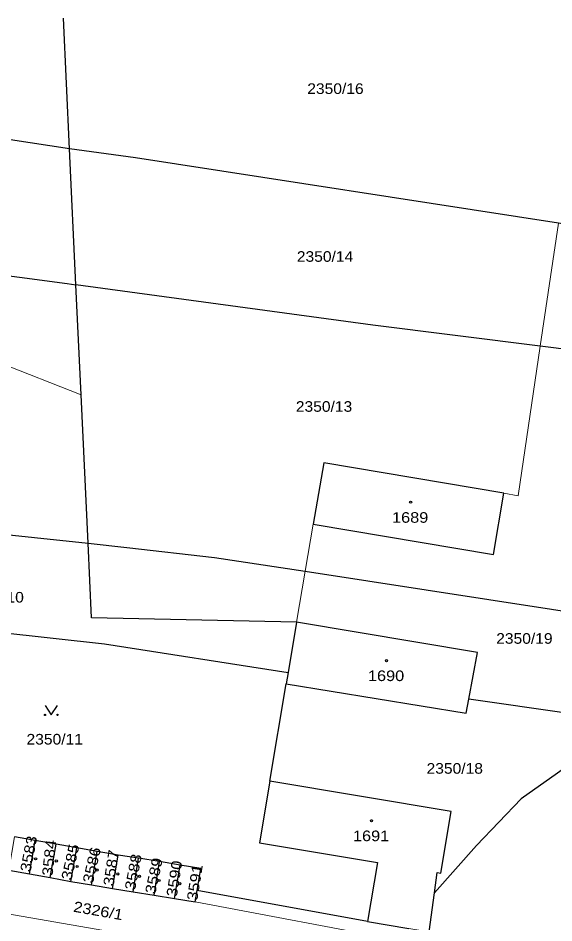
# Model space of a CAD drawing. Extents: x -652394 to -652006, y -1024262 to -1023975.
# Drawn here: x -652262.8 to -652176.9, y -1024121 to -1023975.9 of the extents above; entities that cross this region are included whole.
import ezdxf

# ---------------------------------------------------------------- set-up
doc = ezdxf.new("R2010")
doc.units = 0
doc.header["$LTSCALE"] = 0.46
doc.layers.add('63', color=7, linetype='Continuous', lineweight=25)

msp = doc.modelspace()

# ---------------------------------------------------------------- linework, layer by layer
at = {"layer": '63'}
for p, q in [((-652253.52, -1024018.67), (-652254.55, -1023996.87)), ((-652218.15, -1024072.78), (-652219.51, -1024080.83)), ((-652222.47, -1024098.26), (-652219.82, -1024082.64)), ((-652174.55, -1024087.4), (-652190.57, -1024085.1)), ((-652260.03, -1024107.76), (-652263.39, -1024107.18)), ((-652260.99, -1024113.11), (-652260.03, -1024107.76)), ((-652256.7, -1024108.35), (-652260.03, -1024107.76)), ((-652257.66, -1024113.7), (-652256.7, -1024108.35)), ((-652253.4, -1024108.94), (-652256.7, -1024108.35)), ((-652254.32, -1024114.3), (-652253.4, -1024108.94)), ((-652250.1, -1024109.54), (-652253.4, -1024108.94)), ((-652251.01, -1024114.87), (-652250.1, -1024109.54)), ((-652246.77, -1024110.08), (-652250.1, -1024109.54)), ((-652247.67, -1024115.42), (-652246.77, -1024110.08)), ((-652243.47, -1024110.58), (-652246.77, -1024110.08)), ((-652244.33, -1024115.96), (-652243.47, -1024110.58)), ((-652240.15, -1024111.14), (-652243.47, -1024110.58)), ((-652264.3, -1024112.52), (-652260.99, -1024113.11)), ((-652236.81, -1024111.68), (-652240.15, -1024111.14)), ((-652237.71, -1024117.04), (-652236.81, -1024111.68)), ((-652260.99, -1024113.11), (-652257.66, -1024113.7)), ((-652241.01, -1024116.51), (-652237.71, -1024117.04)), ((-652206.77, -1024120.74), (-652234.11, -1024115.74)), ((-652196.89, -1024122.39), (-652196.06, -1024116.16)), ((-652206.77, -1024120.74), (-652200.18, -1024121.84))]:
    msp.add_line(p, q, dxfattribs=at)
at = {"layer": '63', "lineweight": 13}
for p, q in [((-652179.1, -1024028.51), (-652176.19, -1024008.82)), ((-652316.03, -1024011.45), (-652252.69, -1024036.32)), ((-652182.65, -1024052.49), (-652179.1, -1024028.51)), ((-652184.92, -1024052.11), (-652182.65, -1024052.49)), ((-652216.77, -1024064.61), (-652215.49, -1024057.07)), ((-652218.15, -1024072.78), (-652216.77, -1024064.61)), ((-652306.83, -1024112.26), (-652229.68, -1024125.5))]:
    msp.add_line(p, q, dxfattribs=at)
at = {"layer": '63'}
for points in [[(-652148.27, -1024013.13), (-652170.4, -1024009.72), (-652176.19, -1024008.82), (-652243.97, -1023998.36), (-652254.55, -1023996.87), (-652255.534, -1023975.941)], [(-652254.55, -1023996.87), (-652304.35, -1023989.32), (-652308.54, -1023988.67)], [(-652317.6, -1024010.17), (-652316.1, -1024010.37), (-652254.95, -1024018.48), (-652253.52, -1024018.67)], [(-652251.57, -1024060.11), (-652252.69, -1024036.32), (-652253.52, -1024018.67)], [(-652143.83, -1024032.94), (-652173.61, -1024029.2), (-652179.1, -1024028.51), (-652205.95, -1024025.14), (-652253.52, -1024018.67)], [(-652303.5, -1024054.52), (-652286.04, -1024056.49), (-652251.57, -1024060.11)], [(-652218.15, -1024072.78), (-652251.01, -1024072.09), (-652251.57, -1024060.11)], [(-652251.57, -1024060.11), (-652245.35, -1024060.77), (-652231.31, -1024062.37), (-652216.77, -1024064.61), (-652147.85, -1024075.21)], [(-652312.45, -1024070.27), (-652274.64, -1024073.41), (-652248.96, -1024076.21), (-652219.51, -1024080.83), (-652219.82, -1024082.64)], [(-652190.57, -1024085.1), (-652189.16, -1024077.6), (-652218.15, -1024072.78)], [(-652219.82, -1024082.64), (-652190.99, -1024087.34), (-652190.57, -1024085.1)], [(-652258.48, -1024086.129), (-652257.48, -1024087.63), (-652256.48, -1024086.129)], [(-652168.15, -1024091.02), (-652170.52, -1024092.87), (-652182.16, -1024101.09), (-652189.3, -1024108.53), (-652196.06, -1024116.16)], [(-652222.47, -1024098.26), (-652224.11, -1024108.14), (-652205.17, -1024111.28), (-652206.77, -1024120.74)], [(-652196.06, -1024116.16), (-652195.63, -1024112.89), (-652195.04, -1024112.97), (-652193.37, -1024103.11), (-652222.47, -1024098.26)], [(-652251.01, -1024114.87), (-652247.67, -1024115.42), (-652244.33, -1024115.96), (-652241.01, -1024116.51), (-652240.15, -1024111.14)], [(-652234.11, -1024115.74), (-652233.5, -1024112.24), (-652236.81, -1024111.68)], [(-652257.66, -1024113.7), (-652254.32, -1024114.3), (-652251.01, -1024114.87)], [(-652237.71, -1024117.04), (-652234.43, -1024117.59), (-652234.11, -1024115.74)]]:
    msp.add_lwpolyline(points, dxfattribs=at)
at = {"layer": '63', "lineweight": 13}
for points in [[(-652304.35, -1023989.32), (-652308.54, -1023988.67), (-652308.92, -1023989.69), (-652296.96, -1023994.12), (-652296.17, -1023991.97), (-652292, -1023993.55), (-652294.51, -1024000.29), (-652297.07, -1023999.34), (-652298.69, -1024003.7), (-652306.35, -1024000.82), (-652307.3, -1024008.01), (-652317.85, -1024006.6), (-652317.6, -1024010.17), (-652316.1, -1024010.37), (-652254.95, -1024018.48), (-652253.52, -1024018.67), (-652254.55, -1023996.87)], [(-652243.97, -1023998.36), (-652254.55, -1023996.87), (-652253.52, -1024018.67), (-652205.95, -1024025.14), (-652179.1, -1024028.51), (-652173.61, -1024029.2), (-652143.83, -1024032.94), (-652144.06, -1024031.61), (-652145.01, -1024027.21), (-652151.72, -1024026.09), (-652150.9, -1024021.17), (-652146.15, -1024021.97), (-652146.66, -1024019.59), (-652148.27, -1024013.13), (-652170.4, -1024009.72), (-652176.19, -1024008.82)], [(-652308.71, -1024053.79), (-652308.31, -1024052.74), (-652303.5, -1024054.52), (-652286.04, -1024056.49), (-652251.57, -1024060.11), (-652252.69, -1024036.32), (-652253.52, -1024018.67), (-652254.95, -1024018.48), (-652316.1, -1024010.37), (-652317.6, -1024010.17), (-652317.55, -1024010.86), (-652316.03, -1024011.45), (-652313.5, -1024053.04)], [(-652245.35, -1024060.77), (-652231.31, -1024062.37), (-652216.77, -1024064.61), (-652147.85, -1024075.21), (-652145.21, -1024068.87), (-652171.01, -1024064.48), (-652168.53, -1024049.53), (-652142.12, -1024053.95), (-652141.25, -1024048.05), (-652143.83, -1024032.94), (-652173.61, -1024029.2), (-652179.1, -1024028.51), (-652205.95, -1024025.14), (-652253.52, -1024018.67), (-652252.69, -1024036.32), (-652251.57, -1024060.11)], [(-652184.92, -1024052.11), (-652186.6, -1024061.92), (-652215.49, -1024057.07), (-652213.82, -1024047.21)], [(-652184.92, -1024052.11), (-652213.82, -1024047.21), (-652215.49, -1024057.07), (-652186.6, -1024061.92)], [(-652215.49, -1024057.07), (-652186.6, -1024061.92), (-652184.92, -1024052.11), (-652213.82, -1024047.21)], [(-652251.01, -1024072.09), (-652251.57, -1024060.11), (-652286.04, -1024056.49), (-652303.5, -1024054.52), (-652304.28, -1024056.63), (-652292.3, -1024061.15), (-652291.5, -1024058.99), (-652286.71, -1024060.73), (-652289.26, -1024067.64), (-652292.33, -1024066.48), (-652293.94, -1024070.76), (-652309.34, -1024064.92), (-652307.78, -1024060.79), (-652310.9, -1024059.6), (-652308.71, -1024053.79), (-652313.5, -1024053.04), (-652312.45, -1024070.27), (-652274.64, -1024073.41), (-652248.96, -1024076.21), (-652219.51, -1024080.83), (-652218.15, -1024072.78)], [(-652157.64, -1024082.83), (-652147.85, -1024075.21), (-652216.77, -1024064.61), (-652231.31, -1024062.37), (-652245.35, -1024060.77), (-652251.57, -1024060.11), (-652251.01, -1024072.09), (-652218.15, -1024072.78), (-652189.16, -1024077.6), (-652190.57, -1024085.1), (-652174.55, -1024087.4), (-652173.34, -1024080.12)], [(-652189.16, -1024077.6), (-652218.15, -1024072.78), (-652219.51, -1024080.83), (-652219.82, -1024082.64), (-652190.99, -1024087.34), (-652190.57, -1024085.1)], [(-652219.82, -1024082.64), (-652190.99, -1024087.34), (-652190.57, -1024085.1), (-652189.16, -1024077.6), (-652218.15, -1024072.78), (-652219.51, -1024080.83)], [(-652168.15, -1024091.02), (-652174.96, -1024089.87), (-652174.55, -1024087.4), (-652190.57, -1024085.1), (-652190.99, -1024087.34), (-652219.82, -1024082.64), (-652222.47, -1024098.26), (-652193.37, -1024103.11), (-652195.04, -1024112.97), (-652195.63, -1024112.89), (-652196.06, -1024116.16), (-652189.3, -1024108.53), (-652182.16, -1024101.09), (-652170.52, -1024092.87)], [(-652196.89, -1024122.39), (-652196.06, -1024116.16), (-652195.63, -1024112.89), (-652195.04, -1024112.97), (-652193.37, -1024103.11), (-652222.47, -1024098.26), (-652224.11, -1024108.14), (-652205.17, -1024111.28), (-652206.77, -1024120.74), (-652200.18, -1024121.84)], [(-652224.11, -1024108.14), (-652205.17, -1024111.28), (-652206.77, -1024120.74), (-652200.18, -1024121.84), (-652196.89, -1024122.39), (-652196.06, -1024116.16), (-652195.63, -1024112.89), (-652195.04, -1024112.97), (-652193.37, -1024103.11), (-652222.47, -1024098.26)], [(-652260.99, -1024113.11), (-652260.03, -1024107.76), (-652263.39, -1024107.18), (-652264.3, -1024112.52)], [(-652263.39, -1024107.18), (-652264.3, -1024112.52), (-652260.99, -1024113.11), (-652260.03, -1024107.76)], [(-652256.7, -1024108.35), (-652260.03, -1024107.76), (-652260.99, -1024113.11), (-652257.66, -1024113.7)], [(-652260.99, -1024113.11), (-652257.66, -1024113.7), (-652256.7, -1024108.35), (-652260.03, -1024107.76)], [(-652254.32, -1024114.3), (-652253.4, -1024108.94), (-652256.7, -1024108.35), (-652257.66, -1024113.7)], [(-652256.7, -1024108.35), (-652257.66, -1024113.7), (-652254.32, -1024114.3), (-652253.4, -1024108.94)], [(-652251.01, -1024114.87), (-652250.1, -1024109.54), (-652253.4, -1024108.94), (-652254.32, -1024114.3)], [(-652254.32, -1024114.3), (-652251.01, -1024114.87), (-652250.1, -1024109.54), (-652253.4, -1024108.94)], [(-652246.77, -1024110.08), (-652250.1, -1024109.54), (-652251.01, -1024114.87), (-652247.67, -1024115.42)], [(-652250.1, -1024109.54), (-652251.01, -1024114.87), (-652247.67, -1024115.42), (-652246.77, -1024110.08)], [(-652244.33, -1024115.96), (-652243.47, -1024110.58), (-652246.77, -1024110.08), (-652247.67, -1024115.42)], [(-652247.67, -1024115.42), (-652244.33, -1024115.96), (-652243.47, -1024110.58), (-652246.77, -1024110.08)], [(-652240.15, -1024111.14), (-652243.47, -1024110.58), (-652244.33, -1024115.96), (-652241.01, -1024116.51)], [(-652243.47, -1024110.58), (-652244.33, -1024115.96), (-652241.01, -1024116.51), (-652240.15, -1024111.14)], [(-652237.71, -1024117.04), (-652236.81, -1024111.68), (-652240.15, -1024111.14), (-652241.01, -1024116.51)], [(-652241.01, -1024116.51), (-652237.71, -1024117.04), (-652236.81, -1024111.68), (-652240.15, -1024111.14)], [(-652236.81, -1024111.68), (-652237.71, -1024117.04), (-652234.43, -1024117.59), (-652234.11, -1024115.74), (-652233.5, -1024112.24)], [(-652234.11, -1024115.74), (-652233.5, -1024112.24), (-652236.81, -1024111.68), (-652237.71, -1024117.04), (-652234.43, -1024117.59)]]:
    msp.add_lwpolyline(points, close=True, dxfattribs=at)
at = {"layer": '63'}
msp.add_lwpolyline([(-652184.92, -1024052.11), (-652213.82, -1024047.21), (-652215.49, -1024057.07), (-652186.6, -1024061.92)], close=True, dxfattribs=at)
at = {"layer": '63', "lineweight": 13}
for points in [[(-652263.39, -1024107.18), (-652260.03, -1024107.76), (-652256.7, -1024108.35), (-652253.4, -1024108.94), (-652250.1, -1024109.54), (-652246.77, -1024110.08), (-652243.47, -1024110.58), (-652240.15, -1024111.14), (-652236.81, -1024111.68), (-652233.5, -1024112.24), (-652234.11, -1024115.74), (-652206.77, -1024120.74), (-652205.17, -1024111.28), (-652224.11, -1024108.14), (-652222.47, -1024098.26), (-652219.82, -1024082.64), (-652219.51, -1024080.83), (-652248.96, -1024076.21), (-652274.64, -1024073.41)], [(-652200.18, -1024121.84), (-652206.77, -1024120.74), (-652234.11, -1024115.74), (-652234.43, -1024117.59), (-652237.71, -1024117.04), (-652241.01, -1024116.51), (-652244.33, -1024115.96), (-652247.67, -1024115.42), (-652251.01, -1024114.87), (-652254.32, -1024114.3), (-652257.66, -1024113.7), (-652260.99, -1024113.11), (-652264.3, -1024112.52)], [(-652234.43, -1024117.59), (-652201.01, -1024123.89), (-652197.36, -1024124.55)]]:
    msp.add_lwpolyline(points, dxfattribs=at)
at = {"layer": '63'}
for centre, radius in [((-652199.8868, -1024053.5292), 0.175), ((-652203.7568, -1024078.9392), 0.175), ((-652258.48, -1024087.6295), 0.1), ((-652256.48, -1024087.6295), 0.1), ((-652206.1468, -1024104.5892), 0.175), ((-652259.9868, -1024110.6892), 0.175), ((-652256.6768, -1024111.0292), 0.175), ((-652253.3168, -1024111.9292), 0.175), ((-652250.1168, -1024112.4892), 0.175), ((-652246.8068, -1024113.1092), 0.175), ((-652243.3268, -1024113.4992), 0.175), ((-652240.1868, -1024114.1692), 0.175), ((-652236.8768, -1024114.6792), 0.175)]:
    msp.add_circle(centre, radius, dxfattribs=at)

# ---------------------------------------------------------------- texts
for s, width, p in [('2350/16', 1.1, (-652216.45, -1023988.1)), ('2350/14', 1.1, (-652218.12, -1024015)), ('2350/13', 1.1, (-652218.28, -1024039.04)), ('1689', 1.15, (-652202.867, -1024056.83)), ('2350/10', 1.1, (-652270.91, -1024069.62)), ('2350/19', 1.1, (-652186.17, -1024076.22)), ('1690', 1.15, (-652206.727, -1024082.2)), ('2350/11', 1.1, (-652261.44, -1024092.37)), ('2350/18', 1.1, (-652197.33, -1024097.05)), ('1691', 1.15, (-652209.127, -1024107.86))]:
    msp.add_text(s, height=1.7, dxfattribs=dict(at, width=width)).set_placement(p)
at = {"layer": '63', "width": 1.15}
for s, rotation, p in [('3583', 79, (-652260.814, -1024112.903)), ('3584', 84, (-652257.276, -1024113.522)), ('3585', 77, (-652254.255, -1024114.234)), ('3586', 77, (-652250.815, -1024114.724)), ('3587', 81, (-652247.492, -1024115.149)), ('3588', 79, (-652244.064, -1024115.823)), ('3589', 78, (-652240.809, -1024116.429)), ('3590', 81, (-652237.372, -1024116.869)), ('3591', 81, (-652234.092, -1024117.489)), ('2326/1', 350, (-652254.027, -1024119.147))]:
    msp.add_text(s, height=1.7, rotation=rotation, dxfattribs=at).set_placement(p)

doc.saveas('drawing.dxf')
